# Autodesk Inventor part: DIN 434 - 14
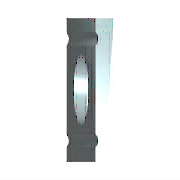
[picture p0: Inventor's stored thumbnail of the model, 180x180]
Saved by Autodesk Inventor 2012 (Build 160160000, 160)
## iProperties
Company: CAD-Verlag
Comments: To add or edit properties for Autodesk Inventor files, use iProperties.
Shininess: 64.0
Length Units: 11269
Angle Units: 11279
Time Units: 11290
Mass Units: 11283
Length Display Precision: 3
Angle Display Precision: 2
Compacted: True
Alert: To add or edit properties for Autodesk Inventor files, use iProperties.
Created: 2004-09
Part Number: DIN 434 - 14
Vendor: Autodesk Inc.
Document SubType Name: Modeling
Designer: Greiling
Material: Standard
Description: U-Scheibe Quadratisch
Standard: DIN 434
Size Designation: 14
Density: 1 g/cm^3
Density: 0.0
Volumn: 0.0
Area: 0.0
PropertySet Name: Model Information
Control State: 0
Master: False
Checked Out: False
Classification: un/spsc 31161802
Author: Jürgen Kronas
Revision Number: 8
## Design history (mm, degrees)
sketch "Skizze1"
  geometry: L1 (-3.7, 15)-(1.2, 15); L2 (1.2, 15)-(-1.2, -15); L3 (-1.2, -15)-(-3.7, -15); L4 (-3.7, 15)-(-3.7, 0); L5 (-3.7, 0)-(-3.7, -15); L6 (-3.7, 0)-(0, 0); 1 further point
  constraints: 12 end point, 1 coincident, 1 collinear, 1 horizontal, 1 midpoint, 1 parallel, 1 perpendicular
  dimensions: "d0" = 15 distance of L1.start L4.end (= 0.5 x SL1); "d1" = 15 distance of L4.end L3.end (= 0.5 x SL1); "d2" = 4.9 distance of L1.start L1.end (= SDB); "d3" = 2.5 distance of L2.end L3.end (computed from SDB, SL1, PIT)
extrude "Körper" new body sketch "Skizze1" stored distance "d4" = 26 (= SL2); taper "d5" = 0 deg
sketch "Skizze3"
  geometry: L1 (3.7, -15)-(-1.2, -15) reference; L2 (3.7, 15)-(3.7, -15) reference; L3 (3, -11)-(3, 11); L4 (-1.69, 0)-(5.17, 0) reference; L5 (3.7, 12.4)-(3.7, 9.6); L6 (1.2, 15)-(3.7, 15) reference; L7 (-1.2, -15)-(1.2, 15) reference; A1 r 1.75 centre (4.75, -11) between (3.7, -9.6) and (3.7, -12.4); A2 r 1.75 centre (4.75, 11) between (3.7, 12.4) and (3.7, 9.6); 2 further points
  constraints: 6 point on circle, 4 end point, 4 symmetric about line, 2 centre point, 2 point on line, 1 collinear, 1 tangent, 1 other
  dimensions: "d6" = 0.7 distance between parallel lines of L2 L3 (= RT); "d7" = 2.6 distance from line of L1 A1.end (= KDIST); "d8" = 2.8 distance of A1.start A1.end (= NB)
extrude "Nut1" cut sketch "Skizze3" taper "d11" = 0 deg; stored distance "d26" = 10
node "Volumenkörper1"
node "Volumenkörpern"
node "Oberflächenkörpern"
sketch "Skizze2"
  geometry: 1 further point
hole "Bohrung" sketch "Skizze2" diameter "d9" = 14 (= SD1); stored, may be unused: countersink angle "d22" = 82 deg, drill point angle "d24" = 118 deg; dims "d19" = 6, "d20" = 4, "d21" = 2, "d23" = 8
fillet "Rundung1" dims "d12" = 2 (= RR)
other parameters: "SD1" = 14 [user parameter; used in 1 equation term], "SL2" = 26 [user parameter; used in 1 equation term], "KDIST" = 2.6 [user parameter; used in 1 equation term], "NB" = 2.8 [user parameter; used in 1 equation term], "RR" = 2 [user parameter; used in 1 equation term], "SDB" = 4.9 [user parameter; used in 2 equation terms], "RT" = 0.7 [user parameter; used in 1 equation term], "d10" = 0, "NND" = 12 [user parameter], "KEWI" = 0.79824 [user parameter]
